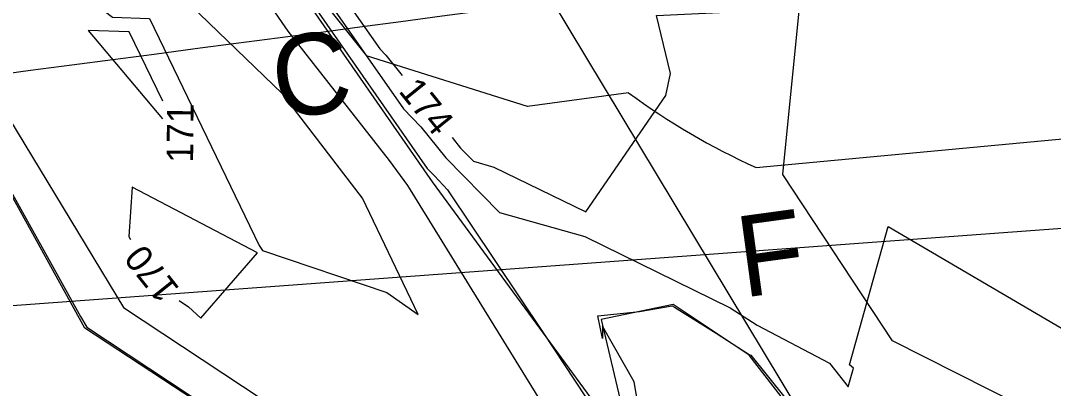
# Model space of a CAD drawing. Extents: x 2086416 to 2115205, y 575507 to 632762.
# Drawn here: x 2111556.7 to 2111634.6, y 581601.8 to 581629.5 of the extents above; entities that cross this region are included whole.
import ezdxf

# ---------------------------------------------------------------- set-up
doc = ezdxf.new("R2010")
doc.units = 0
for name, color, linetype in [('DTM Contours Major', 7, 'Continuous'), ('DTM Contours Major Text', 7, 'Continuous'), ('DTM Contours Minor', 7, 'Continuous'), ('DTM Contours Minor Text', 7, 'Continuous'), ('Exist Hydro Stream or Body of Water', 7, 'Continuous'), ('Exist Hydrographic FEMA Cross Section', 7, 'Continuous'), ('Exist Hydrographic Stream Bed', 7, 'Continuous'), ('Exist Right of Way Line', 7, 'Continuous'), ('Exist Vegetation Woods Line', 7, 'Continuous'), ('Prop SS Cut Line', 7, 'Continuous'), ('Prop SS Cut Text', 7, 'Continuous'), ('Prop SS Fill Line', 7, 'Continuous'), ('Prop SS Fill Text', 7, 'Continuous')]:
    doc.layers.add(name, color=color, linetype=linetype)

msp = doc.modelspace()

# ---------------------------------------------------------------- linework, layer by layer
at = {"layer": 'DTM Contours Major'}
for points in [[(2111561.972, 581631.067), (2111563.648, 581629.772), (2111566.428, 581629.67), (2111574.697, 581612.578), (2111574.966, 581612.195), (2111584.328, 581609.029), (2111586.691, 581607.388), (2111582.492, 581616.152), (2111576.474, 581624.007), (2111569.516, 581630.68), (2111565.57, 581640.043), (2111563.624, 581644.535)], [(2111574.57, 581612.037), (2111565.123, 581616.972), (2111564.883, 581613.251), (2111565.01, 581613.042)], [(2111568.67, 581608.441), (2111569.387, 581607.967), (2111570.316, 581607.11), (2111574.57, 581612.037)]]:
    msp.add_lwpolyline(points, dxfattribs=at)
at = {"layer": 'DTM Contours Minor'}
for points in [[(2111569.01, 581685.022), (2111568.855, 581679.129), (2111567.524, 581675.529), (2111566.521, 581672.948), (2111566.517, 581672.953), (2111566.487, 581672.949), (2111566.146, 581672.893), (2111566.179, 581672.67), (2111567.876, 581660.82), (2111569.433, 581651.069), (2111570.282, 581645.327), (2111570.08, 581645.043), (2111570.701, 581641.072), (2111571.384, 581641.115), (2111571.433, 581641.123), (2111571.418, 581641.253), (2111573.276, 581638.936), (2111576.945, 581633.496), (2111581.656, 581630.446), (2111583.793, 581627.386), (2111584.244, 581626.917), (2111585.478, 581625.384)], [(2111598.535, 581596.664), (2111585.912, 581617.09), (2111584.535, 581618.974), (2111576.895, 581628.719), (2111574.477, 581632.249), (2111572.617, 581634.865), (2111572.402, 581634.572), (2111567.467, 581643.071), (2111567.127, 581645.256), (2111563.317, 581651.146), (2111560.505, 581656.601), (2111559.492, 581657.643), (2111559.123, 581658.446), (2111557.832, 581661.464), (2111555.517, 581665.512)], [(2111589.242, 581620.711), (2111589.877, 581619.921), (2111590.857, 581618.927), (2111592.405, 581618.486), (2111599.33, 581615.104), (2111605.372, 581623.887), (2111605.711, 581625.528), (2111604.66, 581629.897), (2111612.584, 581630.28), (2111613.262, 581630.394), (2111619.383, 581630.749), (2111621.024, 581630.789), (2111642.89, 581633.662), (2111647.196, 581633.15), (2111648.463, 581631.541), (2111653.203, 581633.039), (2111670.864, 581631.971), (2111682.196, 581631.349), (2111685.064, 581615.457), (2111702.133, 581615.465), (2111706.656, 581602.934), (2111726.967, 581593.524), (2111719.652, 581583.63), (2111725.706, 581574.006)], [(2111577.85, 581632.764), (2111579.379, 581631.774), (2111585.586, 581622.885), (2111586.895, 581621.522), (2111588.77, 581619.193), (2111592.833, 581615.071), (2111599.247, 581613.245), (2111610.211, 581607.891), (2111612.256, 581606.571), (2111617.699, 581603.706), (2111619.118, 581601.942), (2111619.518, 581603.35), (2111619.215, 581603.582), (2111621.458, 581611.664), (2111622.113, 581614.012), (2111639.991, 581603.538), (2111640.806, 581603.356), (2111642.077, 581602.394), (2111666.164, 581595.53), (2111674.849, 581575.034)], [(2111578.656, 581630.876), (2111587.378, 581618.383), (2111587.912, 581617.828), (2111588.893, 581616.777), (2111596.136, 581605.984), (2111600.862, 581598.818)], [(2111549.076, 581629.046), (2111561.223, 581607.233), (2111561.714, 581606.423), (2111583.6, 581591.952)], [(2111564.907, 581628.675), (2111561.823, 581628.789), (2111567.42, 581622.114)], [(2111567.432, 581623.456), (2111564.907, 581628.675)], [(2111554.709, 581624.016), (2111564.464, 581607.913), (2111577.893, 581599.034), (2111583.638, 581593.739), (2111584.898, 581595.198), (2111588.199, 581599.364), (2111591.322, 581598.308), (2111596.722, 581594.559), (2111601.884, 581589.387), (2111596.716, 581584.75), (2111593.839, 581583.381), (2111596.471, 581577.936), (2111597.156, 581577.871), (2111597.782, 581578.108), (2111601.297, 581579.615), (2111610.432, 581583.11), (2111617.158, 581580.006), (2111619.199, 581579.456), (2111621.973, 581579.688), (2111624.614, 581575.967), (2111631.966, 581571.272), (2111632.126, 581570.827), (2111633.368, 581570.96)], [(2111603.418, 581599.672), (2111602.97, 581602.317), (2111600.599, 581606.491), (2111600.592, 581605.568), (2111600.223, 581607.27), (2111603.388, 581607.617), (2111605.834, 581608.022), (2111606.011, 581607.938), (2111609.15, 581605.984), (2111611.652, 581604.369), (2111611.759, 581604.313), (2111620.889, 581592.967)]]:
    msp.add_lwpolyline(points, dxfattribs=at)
at = {"layer": 'Exist Hydro Stream or Body of Water'}
for points in [[(2111591.587, 581574.691), (2111583.513, 581582.318), (2111586.645, 581587.276), (2111586.904, 581588.764), (2111586.51, 581589.985), (2111561.568, 581606.344), (2111549.003, 581629.07), (2111542.467, 581641.26), (2111541.348, 581641.183), (2111528.816, 581652.894), (2111524.362, 581663.908), (2111523.315, 581667.748), (2111502.682, 581682.779), (2111481.94, 581698.457), (2111468.579, 581724.282), (2111462.999, 581737.482)], [(2111621.041, 581592.195), (2111611.64, 581604.325), (2111605.912, 581608.14), (2111600.475, 581607.014), (2111602.119, 581600.097), (2111601.107, 581599.205), (2111587.776, 581617.384), (2111576.692, 581633.341), (2111571.484, 581641.081), (2111570.636, 581641.029), (2111569.871, 581645.923), (2111561.21, 581659.642), (2111560.398, 581669.08), (2111561.77, 581674.655), (2111567.139, 581693.151), (2111571.775, 581696.534), (2111557.095, 581714.198), (2111551.353, 581722.025)]]:
    msp.add_lwpolyline(points, dxfattribs=at)
at = {"layer": 'Exist Hydrographic FEMA Cross Section'}
msp.add_lwpolyline([(2112201.875, 581700.225), (2111922.666, 581647.707), (2111776.129, 581636.496), (2111658.777, 581615.589), (2111477.281, 581602.232)], dxfattribs=at)
at = {"layer": 'Exist Hydrographic Stream Bed'}
msp.add_lwpolyline([(2112129.652, 582477.712), (2111835.899, 582368.961), (2111727.147, 582231.15), (2111672.647, 582129.589), (2111610.896, 582009.957), (2111585.646, 581897.526), (2111574.646, 581806.895), (2111574.646, 581727.084), (2111582.896, 581679.524), (2111589.146, 581643.704), (2111621.896, 581589.333), (2111665.397, 581516.772), (2111701.647, 581379.011), (2111737.898, 581248.45), (2111785.148, 581103.388)], dxfattribs=at)
at = {"layer": 'Exist Right of Way Line'}
msp.add_arc((2108326.546, 606231.499), 24816.937, 277.3939111, 277.8562149, dxfattribs=at)
at = {"layer": 'Exist Vegetation Woods Line'}
msp.add_lwpolyline([(2111779.567, 581491.973), (2111763.785, 581504.851), (2111745.339, 581525.059), (2111717.304, 581555.588), (2111690.346, 581575.953), (2111665.09, 581587.143), (2111644.347, 581594.336), (2111622.456, 581605.396), (2111614.175, 581617.919), (2111615.41, 581630.255), (2111644.692, 581636.018), (2111711.675, 581643.899), (2111763.228, 581655.57), (2111785.51, 581656)], dxfattribs=at)
at = {"layer": 'Prop SS Cut Line'}
for p, q in [((2111571.503, 581641.14), (2111582.793, 581626.876)), ((2111594.945, 581623.048), (2111582.793, 581626.876)), ((2111602.546, 581624.086), (2111594.945, 581623.048))]:
    msp.add_line(p, q, dxfattribs=at)
at = {"layer": 'Prop SS Fill Line'}
msp.add_line((2111612.182, 581618.45), (2111675.829, 581624.419), dxfattribs=at)
msp.add_arc((2111634.217, 581667.184), 53.484, 233.6904, 245.67051, dxfattribs=at)

# ---------------------------------------------------------------- texts
at = {"layer": 'DTM Contours Major Text'}
msp.add_text('170', height=2, rotation=128.50068, dxfattribs=at).set_placement((2111568.763, 581609.318))
at = {"layer": 'DTM Contours Minor Text'}
for s, rotation, p in [('174', 308.84383, (2111585.154, 581624.192)), ('171', 89.46087, (2111569.721, 581618.809))]:
    msp.add_text(s, height=2, rotation=rotation, dxfattribs=at).set_placement(p)
at = {"layer": 'Prop SS Cut Text'}
msp.add_text('C', height=6.104, rotation=7.77101, dxfattribs=at).set_placement((2111576.103, 581622.068))
at = {"layer": 'Prop SS Fill Text'}
msp.add_text('F', height=6.104, rotation=7.77101, dxfattribs=at).set_placement((2111611.201, 581608.646))

doc.saveas('drawing.dxf')
